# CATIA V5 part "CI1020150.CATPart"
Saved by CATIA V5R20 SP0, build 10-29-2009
Part number: CI1020150
Bounding box of the stored display mesh (mm): x -20.85 to 22.477, y -19 to 19, z -150 to 45.445
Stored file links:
  C:\Users\Raffaele\Desktop\3D X SITO CF\BOLEX\19-INCLINED ASSEMBLY REF_CI\CI1020150.CATPart
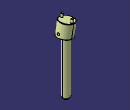
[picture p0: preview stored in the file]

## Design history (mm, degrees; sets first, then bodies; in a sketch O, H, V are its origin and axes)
Set1
  DatumSurface1 to DatumSurface16 "MANIFOLD_SOLID_BREP #387"
  DatumSurface17 to DatumSurface39 "MANIFOLD_SOLID_BREP #1116"
Body1 (main body)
